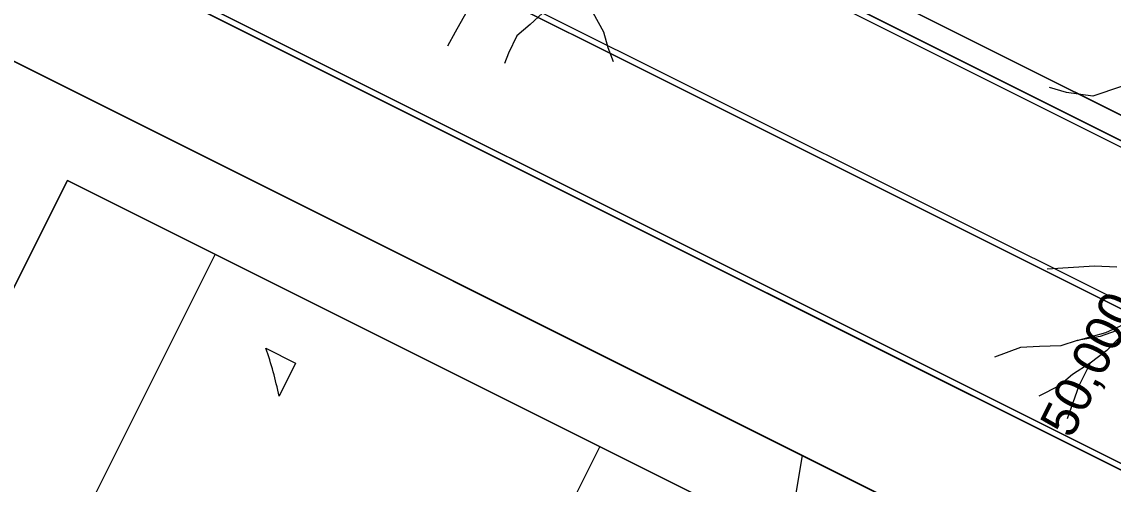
# Model space of a CAD drawing. Extents: x -504998 to -504814, y -1117353 to -1117234.
# Drawn here: x -504939.21 to -504929.95, y -1117268.29 to -1117264.36 of the extents above; entities that cross this region are included whole.
import ezdxf

# ---------------------------------------------------------------- set-up
doc = ezdxf.new("R2010")
doc.units = 0
for name, color, linetype in [('01_ST tenká', 7, 'Continuous'), ('03_POPIS', 7, 'Continuous'), ('10_STROMY', 7, 'Continuous'), ('_01_pl', 7, 'Continuous'), ('_01_sport_plochy', 7, 'Continuous'), ('_01_ST tenká', 7, 'Continuous'), ('_02_pl_ cesta', 7, 'Continuous'), ('Default', 7, 'Continuous')]:
    doc.layers.add(name, color=color, linetype=linetype)

# ---------------------------------------------------------------- blocks, each defined once
blk = doc.blocks.new('stromm')
at = {"layer": 'Default'}
for p, q in [((-0.24111, -0.09557), (-0.26372, -0.10448)), ((-0.28497, -0.10242), (-0.29868, -0.099)), ((-0.26372, -0.10448), (-0.28497, -0.10242)), ((-0.2562, -0.24041), (-0.2939, -0.24452)), ((-0.23838, -0.24041), (-0.2562, -0.24041)), ((-0.22348, -0.28543), (-0.24318, -0.30756)), ((-0.28019, -0.30551), (-0.29733, -0.30688)), ((-0.26725, -0.30058), (-0.28019, -0.30551)), ((-0.31241, -0.30825), (-0.33297, -0.31716)), ((-0.29733, -0.30688), (-0.31241, -0.30825)), ((-0.24318, -0.30756), (-0.2562, -0.31852)), ((-0.2562, -0.31852), (-0.26991, -0.32812)), ((-0.2562, -0.31852), (-0.26442, -0.33703)), ((-0.26991, -0.32812), (-0.28019, -0.33771)), ((-0.28019, -0.33771), (-0.29596, -0.34662)), ((-0.26442, -0.33703), (-0.27265, -0.36376)), ((-0.03874, -0.41111), (-0.04902, -0.43099)), ((0.02355, -0.40928), (0.01096, -0.42208)), ((0.0606, -0.41026), (0.06991, -0.4255)), ((0.01096, -0.42208), (0.00068, -0.43167)), ((0.06991, -0.4255), (0.07403, -0.43784)), ((-0.04902, -0.43099), (-0.05451, -0.44264)), ((0.00068, -0.43167), (-0.00549, -0.44606)), ((-0.00549, -0.44606), (-0.00823, -0.45429)), ((0.07403, -0.43784), (0.07882, -0.4488))]:
    blk.add_line(p, q, dxfattribs=at)
blk.add_lwpolyline([(-0.23661, -0.29149), (-0.24906, -0.29668), (-0.26725, -0.30058), (-0.24469, -0.29318), (-0.23088, -0.28611)], dxfattribs=at)
blk.add_lwpolyline([(-0.23661, -0.29149), (-0.24906, -0.29668), (-0.26725, -0.30058), (-0.24469, -0.29318), (-0.23088, -0.28611)], dxfattribs=at)

msp = doc.modelspace()

# ---------------------------------------------------------------- linework, layer by layer
at = {"layer": '01_ST tenká'}
for p, q in [((-504900.7972, -1117279.6967), (-504948.1838, -1117256.0088)), ((-504939.8496, -1117264.4132), (-504923.7504, -1117272.464)), ((-504938.8211, -1117265.7101), (-504937.5689, -1117266.3363)), ((-504937.5689, -1117266.3363), (-504938.9331, -1117269.0642))]:
    msp.add_line(p, q, dxfattribs=at)
msp.add_lwpolyline([(-504952.9993, -1117290.7085), (-504939.8496, -1117264.4132), (-504923.7504, -1117272.464), (-504936.9001, -1117298.7593)], close=True, dxfattribs=at)
for points in [[(-504945.0828, -1117278.2317), (-504938.8211, -1117265.7101), (-504925.4051, -1117272.4192), (-504931.6668, -1117284.9408)], [(-504934.3044, -1117267.9688), (-504934.3044, -1117267.9688), (-504936.8985, -1117273.1564), (-504932.5159, -1117275.348), (-504929.9218, -1117270.1605)], [(-504932.5884, -1117268.0443), (-504932.9181, -1117270.0037), (-504931.5483, -1117268.5644)]]:
    msp.add_lwpolyline(points, dxfattribs=at)
at = {"layer": '_01_pl'}
msp.add_lwpolyline([(-504937.1881, -1117248.33), (-504911.1347, -1117267.929), (-504901.2482, -1117274.9388), (-504900.5935, -1117275.3475), (-504902.3736, -1117278.9087), (-504942.9722, -1117258.614), (-504941.0946, -1117254.858), (-504941.0341, -1117254.737)], close=True, dxfattribs=at)
for points in [[(-504948.1838, -1117256.0088), (-504883.1034, -1117288.5416), (-504884.4448, -1117291.225), (-504886.0794, -1117290.4079), (-504886.0783, -1117290.4057), (-504900.5273, -1117283.1828), (-504900.8848, -1117283.898), (-504903.7177, -1117282.4818), (-504910.4257, -1117279.1273), (-504909.9784, -1117278.2329), (-504912.6616, -1117276.8911), (-504913.1089, -1117277.7855), (-504939.8496, -1117264.4132)], [(-504949.3862, -1117258.4143), (-504884.5343, -1117290.8451), (-504883.4161, -1117288.6091), (-504948.2684, -1117256.1781)]]:
    msp.add_lwpolyline(points, dxfattribs=at)
at = {"layer": '_01_sport_plochy'}
for points in [[(-504884.8258, -1117287.9042), (-504885.9439, -1117290.1402), (-504948.552, -1117258.8314), (-504947.4338, -1117256.5954)], [(-504885.9663, -1117290.0731), (-504948.4849, -1117258.8091), (-504947.9593, -1117257.7582), (-504885.4408, -1117289.0222)], [(-504885.4408, -1117289.0222), (-504947.9593, -1117257.7582), (-504948.4849, -1117258.8091), (-504885.9663, -1117290.0731)], [(-504939.8496, -1117264.4132), (-504923.7504, -1117272.464), (-504936.9001, -1117298.7593), (-504952.9993, -1117290.7085)], [(-504951.3446, -1117290.7533), (-504937.9286, -1117297.4624), (-504925.4051, -1117272.4192), (-504938.8211, -1117265.7101)], [(-504951.3446, -1117290.7533), (-504937.9286, -1117297.4624), (-504925.4051, -1117272.4192), (-504938.8211, -1117265.7101)]]:
    msp.add_lwpolyline(points, close=True, dxfattribs=at)
at = {"layer": '_01_ST tenká'}
for p, q in [((-504947.937, -1117257.7134), (-504885.4184, -1117288.9775)), ((-504947.9593, -1117257.7582), (-504885.4408, -1117289.0222))]:
    msp.add_line(p, q, dxfattribs=at)
msp.add_lwpolyline([(-504951.6824, -1117257.266), (-504885.9439, -1117290.1402), (-504884.8258, -1117287.9042), (-504950.5642, -1117255.03)], close=True, dxfattribs=at)
for points in [[(-504885.4184, -1117288.9775), (-504884.8929, -1117287.9265), (-504947.4114, -1117256.6625)], [(-504948.4849, -1117258.8091), (-504885.9663, -1117290.0731), (-504885.4408, -1117289.0222)]]:
    msp.add_lwpolyline(points, dxfattribs=at)
at = {"layer": '_02_pl_ cesta'}
msp.add_lwpolyline([(-504937.1386, -1117267.1329), (-504936.8855, -1117267.2595), (-504937.0259, -1117267.5403)], dxfattribs=at)
msp.add_arc((-504940.4388, -1117268.2648), 3.489, 11.98466, 18.93079, dxfattribs=at)

# ---------------------------------------------------------------- block references
at = {"layer": '10_STROMY', "xscale": 10.58270031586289, "yscale": 10.582699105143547, "rotation": -2.5987541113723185}
for p in [(-504934.8086, -1117259.9181), (-504927.2851, -1117264.0178)]:
    msp.add_blockref('stromm', p, dxfattribs=at)

# ---------------------------------------------------------------- texts
at = {"layer": '03_POPIS'}
msp.add_text('50,000', height=0.31278, rotation=63.36718, dxfattribs=at).set_placement((-504930.3043, -1117267.9093))

doc.saveas('drawing.dxf')
